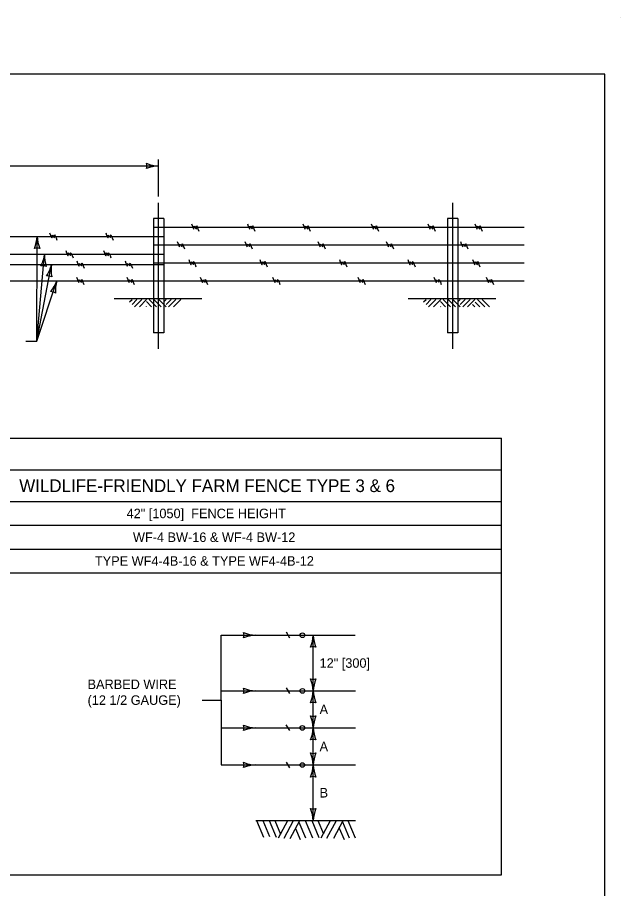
# Model space of a CAD drawing. Extents: x 49991.4 to 50021, y 49987.6 to 50011.4.
# Drawn here: x 50017.23 to 50021.04, y 50003.02 to 50008.52 of the extents above; entities that cross this region are included whole.
import ezdxf

# ---------------------------------------------------------------- set-up
doc = ezdxf.new("R2010")
doc.units = 0
for name, color, linetype in [('Level 1', 7, 'Continuous'), ('Level 2', 7, 'Continuous'), ('Level 3', 7, 'Continuous'), ('Level 4', 7, 'Continuous'), ('Level 5', 7, 'Continuous')]:
    doc.layers.add(name, color=color, linetype=linetype)

msp = doc.modelspace()

# ---------------------------------------------------------------- linework, layer by layer
at = {"layer": 'Level 1'}
for p, q in [((50021.0378, 50008.5236), (50021.0378, 50008.5236)), ((50021.0378, 50008.5236), (50021.0378, 50008.5236)), ((50018.0891, 50007.2536), (50018.0891, 50006.7473)), ((50018.1548, 50007.2536), (50018.0891, 50007.2536)), ((50018.1548, 50007.2536), (50018.1548, 50006.7473)), ((50019.9454, 50007.2536), (50019.9454, 50006.7473)), ((50020.0111, 50007.2536), (50019.9454, 50007.2536)), ((50020.0111, 50007.2536), (50020.0111, 50006.7473)), ((50020.4293, 50007.1973), (50018.0891, 50007.1973)), ((50012.5204, 50007.1411), (50018.1548, 50007.1411)), ((50020.4293, 50007.0848), (50018.0891, 50007.0848)), ((50012.5204, 50007.0286), (50018.1548, 50007.0286)), ((50012.5204, 50006.963), (50018.1548, 50006.963)), ((50020.4293, 50006.9723), (50018.0891, 50006.9723)), ((50010.2459, 50006.8598), (50020.4293, 50006.8598)), ((50018.3943, 50006.7473), (50017.8417, 50006.7473)), ((50017.9386, 50006.7273), (50017.954, 50006.7427)), ((50017.954, 50006.7118), (50017.9849, 50006.7427)), ((50017.9694, 50006.6964), (50018.0157, 50006.7427)), ((50018.0003, 50006.6964), (50018.0465, 50006.7427)), ((50018.1082, 50006.6964), (50018.0619, 50006.7427)), ((50018.1082, 50006.6964), (50018.0619, 50006.7427)), ((50018.139, 50006.6964), (50018.0928, 50006.7427)), ((50018.139, 50006.6964), (50018.0928, 50006.7427)), ((50018.1699, 50006.6964), (50018.1236, 50006.7427)), ((50018.1699, 50006.6964), (50018.1236, 50006.7427)), ((50018.1545, 50006.7273), (50018.1699, 50006.7427)), ((50018.1699, 50006.7118), (50018.2007, 50006.7427)), ((50018.1853, 50006.6964), (50018.2316, 50006.7427)), ((50018.2161, 50006.6964), (50018.2624, 50006.7427)), ((50020.2505, 50006.7473), (50019.6979, 50006.7473)), ((50019.7948, 50006.7273), (50019.8103, 50006.7427)), ((50019.8103, 50006.7118), (50019.8411, 50006.7427)), ((50019.8257, 50006.6964), (50019.8719, 50006.7427)), ((50019.8565, 50006.6964), (50019.9028, 50006.7427)), ((50019.9645, 50006.6964), (50019.9182, 50006.7427)), ((50019.9645, 50006.6964), (50019.9182, 50006.7427)), ((50019.9953, 50006.6964), (50019.949, 50006.7427)), ((50019.9953, 50006.6964), (50019.949, 50006.7427)), ((50020.0261, 50006.6964), (50019.9799, 50006.7427)), ((50020.0261, 50006.6964), (50019.9799, 50006.7427)), ((50020.0107, 50006.7273), (50020.0261, 50006.7427)), ((50020.0261, 50006.7118), (50020.057, 50006.7427)), ((50020.0415, 50006.6964), (50020.0878, 50006.7427)), ((50020.0724, 50006.6964), (50020.1186, 50006.7427)), ((50020.1803, 50006.6964), (50020.1341, 50006.7427)), ((50020.1803, 50006.6964), (50020.1341, 50006.7427)), ((50020.2112, 50006.6964), (50020.1649, 50006.7427)), ((50020.2112, 50006.6964), (50020.1649, 50006.7427)), ((50018.0774, 50006.6964), (50018.0445, 50006.7303)), ((50018.0774, 50006.6964), (50018.0445, 50006.7303)), ((50018.0465, 50006.6964), (50018.0445, 50006.6995)), ((50019.9336, 50006.6964), (50019.9007, 50006.7303)), ((50019.9336, 50006.6964), (50019.9007, 50006.7303)), ((50019.9028, 50006.6964), (50019.9007, 50006.6995)), ((50020.1186, 50006.6964), (50020.1032, 50006.7118)), ((50020.1495, 50006.6964), (50020.1197, 50006.7262)), ((50018.7346, 50004.6229), (50019.3633, 50004.6229)), ((50018.9502, 50004.6053), (50018.9282, 50004.6414)), ((50018.7346, 50004.272), (50019.3653, 50004.272)), ((50018.9502, 50004.2556), (50018.9282, 50004.2917)), ((50018.9502, 50004.0216), (50018.9281, 50004.0578)), ((50018.7346, 50004.038), (50019.3653, 50004.038)), ((50018.7346, 50003.804), (50019.3653, 50003.804)), ((50018.9502, 50003.7863), (50018.9282, 50003.8224)), ((50018.7346, 50003.4531), (50019.3653, 50003.4531)), ((50018.7405, 50003.4531), (50018.7843, 50003.3492)), ((50018.7802, 50003.4531), (50018.8229, 50003.3518)), ((50018.8205, 50003.4531), (50018.8642, 50003.3492)), ((50018.8554, 50003.4531), (50018.8916, 50003.3671)), ((50018.8791, 50003.3438), (50018.9379, 50003.4531)), ((50018.9135, 50003.3421), (50018.9732, 50003.4531)), ((50018.9521, 50003.3404), (50019.0127, 50003.4531)), ((50019.0076, 50003.4435), (50019.0499, 50003.3432)), ((50019.0473, 50003.4531), (50019.0929, 50003.3449)), ((50019.0881, 50003.4531), (50019.1333, 50003.3457)), ((50019.1263, 50003.4531), (50019.1618, 50003.3686)), ((50019.1489, 50003.3446), (50019.2074, 50003.4531)), ((50019.184, 50003.3421), (50019.2439, 50003.4531)), ((50019.228, 50003.3421), (50019.2877, 50003.4531)), ((50019.2831, 50003.4444), (50019.3257, 50003.3432)), ((50019.3167, 50003.4531), (50019.3627, 50003.344)), ((50018.9861, 50003.4034), (50019.0153, 50003.3341)), ((50019.2621, 50003.4057), (50019.293, 50003.3324))]:
    msp.add_line(p, q, dxfattribs=at)
msp.add_lwpolyline([(50020.9378, 50008.1646), (50009.7374, 50008.1646), (50009.7374, 49999.8856), (50020.9378, 49999.8856)], close=True, dxfattribs=at)
msp.add_lwpolyline([(50020.9378, 50008.1646), (50009.7374, 50008.1646), (50009.7374, 49999.8856), (50020.9378, 49999.8856)], close=True, dxfattribs=at)
for centre in [(50019.0298, 50004.6228), (50019.0298, 50004.2718), (50019.0297, 50004.0379), (50019.0297, 50003.8039)]:
    msp.add_circle(centre, 0.0146, dxfattribs=at)
for points in [[(50018.3297, 50007.2204), (50018.3452, 50007.1895), (50018.3452, 50007.205), (50018.3606, 50007.1895), (50018.3606, 50007.205), (50018.376, 50007.1741)], [(50018.6825, 50007.2204), (50018.6979, 50007.1895), (50018.6979, 50007.205), (50018.7133, 50007.1895), (50018.7133, 50007.205), (50018.7287, 50007.1741)], [(50019.0325, 50007.2204), (50019.0479, 50007.1895), (50019.0479, 50007.205), (50019.0634, 50007.1895), (50019.0634, 50007.205), (50019.0788, 50007.1741)], [(50019.4636, 50007.2204), (50019.479, 50007.1895), (50019.479, 50007.205), (50019.4945, 50007.1895), (50019.4945, 50007.205), (50019.5099, 50007.1741)], [(50019.8216, 50007.2204), (50019.837, 50007.1895), (50019.837, 50007.205), (50019.8524, 50007.1895), (50019.8524, 50007.205), (50019.8678, 50007.1741)], [(50020.1178, 50007.2204), (50020.1332, 50007.1895), (50020.1332, 50007.205), (50020.1486, 50007.1895), (50020.1486, 50007.205), (50020.164, 50007.1741)], [(50017.4339, 50007.1642), (50017.4493, 50007.1334), (50017.4493, 50007.1488), (50017.4647, 50007.1334), (50017.4647, 50007.1488), (50017.4801, 50007.118)], [(50017.788, 50007.1642), (50017.8035, 50007.1334), (50017.8035, 50007.1488), (50017.8189, 50007.1334), (50017.8189, 50007.1488), (50017.8343, 50007.118)], [(50018.2388, 50007.1079), (50018.2542, 50007.0771), (50018.2542, 50007.0925), (50018.2696, 50007.0771), (50018.2696, 50007.0925), (50018.2851, 50007.0617)], [(50018.6657, 50007.1079), (50018.6811, 50007.0771), (50018.6811, 50007.0925), (50018.6966, 50007.0771), (50018.6966, 50007.0925), (50018.712, 50007.0617)], [(50019.1267, 50007.1079), (50019.1421, 50007.0771), (50019.1421, 50007.0925), (50019.1575, 50007.0771), (50019.1575, 50007.0925), (50019.173, 50007.0617)], [(50019.5579, 50007.1079), (50019.5733, 50007.0771), (50019.5733, 50007.0925), (50019.5888, 50007.0771), (50019.5888, 50007.0925), (50019.6042, 50007.0617)], [(50020.0269, 50007.1079), (50020.0423, 50007.0771), (50020.0423, 50007.0925), (50020.0577, 50007.0771), (50020.0577, 50007.0925), (50020.0731, 50007.0617)], [(50017.5354, 50007.0517), (50017.5508, 50007.0209), (50017.5508, 50007.0363), (50017.5663, 50007.0209), (50017.5663, 50007.0363), (50017.5817, 50007.0055)], [(50017.7747, 50007.0517), (50017.7901, 50007.0209), (50017.7901, 50007.0363), (50017.8055, 50007.0209), (50017.8055, 50007.0363), (50017.8209, 50007.0055)], [(50017.605, 50006.9861), (50017.6205, 50006.9553), (50017.6205, 50006.9707), (50017.6359, 50006.9553), (50017.6359, 50006.9707), (50017.6513, 50006.9398)], [(50017.9101, 50006.9861), (50017.9255, 50006.9553), (50017.9255, 50006.9707), (50017.9409, 50006.9553), (50017.9409, 50006.9707), (50017.9563, 50006.9398)], [(50018.3117, 50006.9954), (50018.3271, 50006.9646), (50018.3271, 50006.98), (50018.3425, 50006.9646), (50018.3425, 50006.98), (50018.3579, 50006.9492)], [(50018.7602, 50006.9954), (50018.7756, 50006.9646), (50018.7756, 50006.98), (50018.791, 50006.9646), (50018.791, 50006.98), (50018.8064, 50006.9492)], [(50019.2629, 50006.9954), (50019.2783, 50006.9646), (50019.2783, 50006.98), (50019.2938, 50006.9646), (50019.2938, 50006.98), (50019.3092, 50006.9492)], [(50019.6942, 50006.9954), (50019.7096, 50006.9646), (50019.7096, 50006.98), (50019.725, 50006.9646), (50019.725, 50006.98), (50019.7404, 50006.9492)], [(50020.1029, 50006.9954), (50020.1183, 50006.9646), (50020.1183, 50006.98), (50020.1338, 50006.9646), (50020.1338, 50006.98), (50020.1492, 50006.9492)], [(50017.6034, 50006.8829), (50017.6189, 50006.8521), (50017.6189, 50006.8675), (50017.6343, 50006.8521), (50017.6343, 50006.8675), (50017.6497, 50006.8367)], [(50017.9217, 50006.8829), (50017.9371, 50006.8521), (50017.9371, 50006.8675), (50017.9525, 50006.8521), (50017.9525, 50006.8675), (50017.9679, 50006.8367)], [(50018.3847, 50006.8829), (50018.4001, 50006.8521), (50018.4001, 50006.8675), (50018.4155, 50006.8521), (50018.4155, 50006.8675), (50018.431, 50006.8367)], [(50018.8417, 50006.8829), (50018.8571, 50006.8521), (50018.8571, 50006.8675), (50018.8725, 50006.8521), (50018.8725, 50006.8675), (50018.888, 50006.8367)], [(50019.3796, 50006.8829), (50019.3951, 50006.8521), (50019.3951, 50006.8675), (50019.4105, 50006.8521), (50019.4105, 50006.8675), (50019.4259, 50006.8367)], [(50019.8601, 50006.8829), (50019.8755, 50006.8521), (50019.8755, 50006.8675), (50019.8909, 50006.8521), (50019.8909, 50006.8675), (50019.9064, 50006.8367)], [(50020.1899, 50006.8829), (50020.2053, 50006.8521), (50020.2053, 50006.8675), (50020.2207, 50006.8521), (50020.2207, 50006.8675), (50020.2361, 50006.8367)]]:
    msp.add_spline(points, degree=3, dxfattribs=at)
at = {"layer": 'Level 2'}
for p, q in [((50010.3885, 50005.867), (50020.2867, 50005.867)), ((50020.2867, 50003.11), (50020.2867, 50005.867)), ((50010.3885, 50005.667), (50020.2867, 50005.667)), ((50010.3885, 50005.467), (50020.2867, 50005.467)), ((50010.3885, 50005.317), (50020.2867, 50005.317)), ((50010.3885, 50005.167), (50020.2867, 50005.167)), ((50010.3885, 50005.017), (50020.2867, 50005.017)), ((50010.3885, 50003.11), (50020.2867, 50003.11))]:
    msp.add_line(p, q, dxfattribs=at)
at = {"layer": 'Level 3'}
for p, q in [((50018.122, 50007.3936), (50018.122, 50007.6257)), ((50012.5532, 50007.5857), (50018.122, 50007.5857)), ((50017.3536, 50006.4793), (50017.3551, 50007.1411)), ((50017.3536, 50006.4793), (50017.4026, 50007.0286)), ((50017.3536, 50006.4793), (50017.4456, 50006.963)), ((50017.3536, 50006.4793), (50017.4791, 50006.8598)), ((50017.2836, 50006.4793), (50017.3536, 50006.4793)), ((50018.5164, 50004.6229), (50018.7298, 50004.6229)), ((50018.5164, 50004.6229), (50018.7346, 50004.6229)), ((50018.518, 50003.804), (50018.5164, 50004.6229)), ((50019.0981, 50004.272), (50019.0981, 50004.6229)), ((50019.0981, 50004.272), (50019.0981, 50004.6229)), ((50018.5164, 50004.272), (50018.7346, 50004.272)), ((50019.0981, 50004.038), (50019.0981, 50004.272)), ((50018.3962, 50004.2135), (50018.5172, 50004.2135)), ((50018.5175, 50004.0379), (50018.7346, 50004.038)), ((50019.098, 50003.8039), (50019.098, 50004.038)), ((50018.5164, 50003.804), (50018.7298, 50003.804)), ((50018.5164, 50003.804), (50018.7346, 50003.804)), ((50019.098, 50003.4531), (50019.098, 50003.804))]:
    msp.add_line(p, q, dxfattribs=at)
for centre, radius, start, end in [((50018.1311, 50007.8078), 0.2223, 247.456, 267.6395), ((50017.9938, 50007.5857), 0.0548, 342.1388, 17.8612), ((50018.1335, 50007.353), 0.233, 92.8273, 112.0772), ((50017.1224, 50007.1531), 0.233, 337.7941, 357.044), ((50017.5773, 50007.1497), 0.2223, 182.2318, 202.4153), ((50017.3548, 50007.0129), 0.0548, 72.0101, 107.7325), ((50017.1718, 50007.0607), 0.233, 332.8324, 352.0823), ((50017.6246, 50007.018), 0.2223, 177.2701, 197.4536), ((50017.2191, 50007.0177), 0.233, 327.159, 346.4088), ((50017.6655, 50006.9305), 0.2223, 171.5966, 191.7801), ((50017.3912, 50006.9009), 0.0548, 67.0484, 102.7708), ((50017.4216, 50006.837), 0.0548, 61.375, 97.0973), ((50017.2617, 50006.9436), 0.233, 319.6776, 338.9275), ((50017.6929, 50006.7989), 0.2223, 164.1153, 184.2988), ((50017.4389, 50006.738), 0.0548, 53.8936, 89.616), ((50018.7438, 50004.8451), 0.2223, 247.456, 267.6395), ((50018.6064, 50004.6229), 0.0548, 342.1388, 17.8612), ((50018.7461, 50004.3902), 0.233, 92.8273, 112.0772), ((50018.8653, 50004.6344), 0.233, 337.9228, 357.1727), ((50019.3202, 50004.6321), 0.2223, 182.3605, 202.544), ((50019.0981, 50004.4947), 0.0548, 72.1388, 107.8612), ((50018.8759, 50004.2628), 0.2223, 2.3605, 22.544), ((50019.0981, 50004.4002), 0.0548, 252.1388, 287.8612), ((50019.3308, 50004.2605), 0.233, 157.9228, 177.1727), ((50018.7438, 50004.4941), 0.2223, 247.456, 267.6395), ((50018.6064, 50004.272), 0.0548, 342.1388, 17.8612), ((50018.7461, 50004.0393), 0.233, 92.8273, 112.0772), ((50018.8653, 50004.2835), 0.233, 337.9228, 357.1727), ((50019.3202, 50004.2811), 0.2223, 182.3605, 202.544), ((50019.0981, 50004.1438), 0.0548, 72.1388, 107.8612), ((50018.8759, 50004.0289), 0.2223, 2.3605, 22.544), ((50019.0981, 50004.1662), 0.0548, 252.1388, 287.8612), ((50019.3308, 50004.0265), 0.233, 157.9228, 177.1727), ((50018.7438, 50004.2601), 0.2223, 247.456, 267.6395), ((50018.6064, 50004.038), 0.0548, 342.1388, 17.8612), ((50018.7461, 50003.8053), 0.233, 92.8273, 112.0772), ((50018.8653, 50004.0495), 0.233, 337.9228, 357.1727), ((50019.3201, 50004.0472), 0.2223, 182.3605, 202.544), ((50019.098, 50003.9098), 0.0548, 72.1388, 107.8612), ((50018.8759, 50003.7948), 0.2223, 2.3605, 22.544), ((50019.098, 50003.9321), 0.0548, 252.1388, 287.8612), ((50019.3307, 50003.7924), 0.233, 157.9228, 177.1727), ((50018.7438, 50004.0262), 0.2223, 247.456, 267.6395), ((50018.6064, 50003.804), 0.0548, 342.1388, 17.8612), ((50018.7461, 50003.5713), 0.233, 92.8273, 112.0772), ((50018.8653, 50003.8155), 0.233, 337.9228, 357.1727), ((50019.3201, 50003.8132), 0.2223, 182.3605, 202.544), ((50019.098, 50003.6758), 0.0548, 72.1388, 107.8612), ((50018.8759, 50003.4439), 0.2223, 2.3605, 22.544), ((50019.098, 50003.5813), 0.0548, 252.1388, 287.8612), ((50019.3307, 50003.4416), 0.233, 157.9228, 177.1727)]:
    msp.add_arc(centre, radius, start, end, dxfattribs=at)
at = {"layer": 'Level 4'}
for p, q in [((50018.0891, 50006.7473), (50018.0891, 50006.5317)), ((50018.1548, 50006.7473), (50018.1548, 50006.5317)), ((50019.9454, 50006.7473), (50019.9454, 50006.5317)), ((50020.0111, 50006.7473), (50020.0111, 50006.5317)), ((50018.1548, 50006.5317), (50018.0891, 50006.5317)), ((50020.0111, 50006.5317), (50019.9454, 50006.5317))]:
    msp.add_line(p, q, dxfattribs=at)
at = {"layer": 'Level 5'}
for p, q in [((50018.122, 50006.4316), (50018.122, 50007.3536)), ((50019.9782, 50006.4316), (50019.9782, 50007.3536))]:
    msp.add_line(p, q, dxfattribs=at)

# ---------------------------------------------------------------- texts
at = {"layer": 'Level 2'}
for s, height, p in [('WILDLIFE-FRIENDLY FARM FENCE TYPE 3 & 6', 0.08, (50017.2422, 50005.527)), ('42" [1050]  FENCE HEIGHT', 0.06, (50017.92, 50005.362)), ('WF-4 BW-16 & WF-4 BW-12', 0.06, (50017.96, 50005.212)), ('TYPE WF4-4B-16 & TYPE WF4-4B-12', 0.06, (50017.72, 50005.062)), ('12" [300]', 0.06, (50019.1381, 50004.4175)), ('BARBED WIRE', 0.06, (50017.6737, 50004.2835)), ('(12 1/2 GAUGE)', 0.06, (50017.6737, 50004.1835)), ('A', 0.06, (50019.1381, 50004.125)), ('A', 0.06, (50019.138, 50003.8909)), ('B', 0.06, (50019.138, 50003.5985))]:
    msp.add_text(s, height=height, dxfattribs=at).set_placement(p)

doc.saveas('drawing.dxf')
